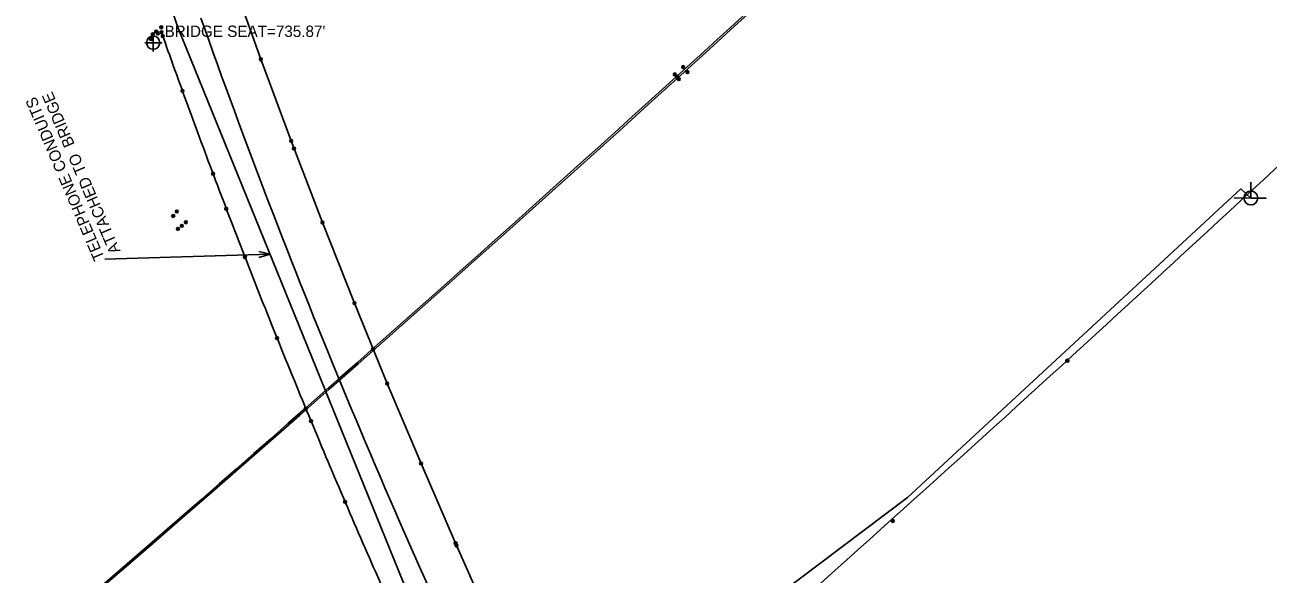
# Model space of a CAD drawing. Extents: x 1550153 to 1552579, y 809637 to 812160.
# Drawn here: x 1551716.6 to 1552155.6, y 810663.3 to 810857.2 of the extents above; entities that cross this region are included whole.
import ezdxf

# ---------------------------------------------------------------- set-up
doc = ezdxf.new("R2010")
doc.units = 0
for name, color, linetype in [('Default', 7, 'Continuous'), ('E_NCDOT_Horizontal_Alignment_Curve', 7, 'Continuous'), ('E_NCDOT_Horizontal_Alignment_Tick_Label', 7, 'Continuous'), ('Exist Right of Way Line', 7, 'Continuous'), ('Exist Roads EOP Other', 7, 'Continuous'), ('Exist Structure Major Bridge Seat Cogo Point CELL', 7, 'Continuous'), ('Exist Utilities Power Joint Use Telephone CELL', 7, 'Continuous'), ('Exist Utilities Telephone Text', 7, 'Continuous'), ('Exist Utilities Telephone UG Cable SUE LOS B', 7, 'Continuous'), ('Exist Utilities Telephone UG Cable SUE LOS C', 7, 'Continuous'), ('Exist Utilities Telephone UG FO SUE LOS B', 7, 'Continuous')]:
    doc.layers.add(name, color=color, linetype=linetype)

# ---------------------------------------------------------------- blocks, each defined once
blk = doc.blocks.new('SurveyPointCell')
at = {"layer": 'Default'}
for p, q in [((-0.5, 0), (0.5, 0)), ((0, -0.5), (0, 0.5))]:
    blk.add_line(p, q, dxfattribs=at)
blk.add_circle((0, 0), 0.5, dxfattribs=at)

msp = doc.modelspace()

# ---------------------------------------------------------------- linework, layer by layer
at = {"layer": 'Default'}
msp.add_line((1551761.92, 810850.87), (1551761.92, 810850.87), dxfattribs=at)
msp.add_arc((1544558.52, 818987.58), 11000, 308.905285, 313.48368, dxfattribs=at)
msp.add_arc((1544558.52, 818987.58), 11000, 308.905285, 313.48368, dxfattribs=at)
at = {"layer": 'E_NCDOT_Horizontal_Alignment_Curve'}
for centre, radius, start, end in [((1544245.73, 819324.67), 11459.16, 307.933611, 313.133611), ((1544245.73, 819324.67), 11459.16, 307.933611, 313.133611), ((1554277.17, 811742.97), 2650, 199.47344, 205.4841), ((1554277.17, 811742.97), 2650, 199.47344, 205.4841)]:
    msp.add_arc(centre, radius, start, end, dxfattribs=at)
at = {"layer": 'E_NCDOT_Horizontal_Alignment_Tick_Label'}
msp.add_arc((1544558.52, 818987.58), 11000, 308.905285, 313.48368, dxfattribs=at)
at = {"layer": 'Exist Right of Way Line'}
msp.add_arc((1544245.71, 819324.7), 11626.16, 311.427072, 313.124848, dxfattribs=at)
at = {"layer": 'Exist Roads EOP Other'}
for p, q in [((1551789.07, 810875.41), (1551799.93, 810844.99)), ((1551789.07, 810875.41), (1551799.93, 810844.99)), ((1551765.33, 810853.14), (1551764.85, 810854.54)), ((1551765.33, 810853.14), (1551764.85, 810854.54)), ((1551799.93, 810844.99), (1551810.62, 810816.24)), ((1551799.93, 810844.99), (1551810.62, 810816.24)), ((1551810.62, 810816.24), (1551821.7, 810787.42)), ((1551810.62, 810816.24), (1551821.7, 810787.42)), ((1551821.7, 810787.42), (1551832.98, 810758.95)), ((1551821.7, 810787.42), (1551832.98, 810758.95)), ((1551832.98, 810758.95), (1551844.52, 810730.57)), ((1551832.98, 810758.95), (1551844.52, 810730.57)), ((1551844.52, 810730.57), (1551856.47, 810702.36)), ((1551844.52, 810730.57), (1551856.47, 810702.36)), ((1551856.47, 810702.36), (1551868.68, 810674.18)), ((1551856.47, 810702.36), (1551868.68, 810674.18)), ((1551868.68, 810674.18), (1551881.33, 810645.63)), ((1551868.68, 810674.18), (1551881.33, 810645.63))]:
    msp.add_line(p, q, dxfattribs=at)
msp.add_open_spline([(1551864.83, 810610.13), (1551863.85, 810612.31), (1551860.28, 810619.56), (1551853.04, 810635.92), (1551842.19, 810659.92), (1551829.81, 810688.31), (1551817.52, 810717.53), (1551805.7, 810746.3), (1551794.16, 810775.4), (1551783.02, 810804.5), (1551773.45, 810830.52), (1551767.56, 810846.7), (1551765.33, 810853.14)], degree=3, dxfattribs=at)
msp.add_open_spline([(1551864.83, 810610.13), (1551863.85, 810612.31), (1551860.28, 810619.56), (1551853.04, 810635.92), (1551842.19, 810659.92), (1551829.81, 810688.31), (1551817.52, 810717.53), (1551805.7, 810746.3), (1551794.16, 810775.4), (1551783.02, 810804.5), (1551773.45, 810830.52), (1551767.56, 810846.7), (1551765.33, 810853.14)], degree=3, dxfattribs=at)
at = {"layer": 'Exist Structure Major Bridge Seat Cogo Point CELL'}
msp.add_lwpolyline([(1551761.92, 810853.87), (1551761.92, 810847.87), (1551761.92, 810850.87), (1551764.92, 810850.87), (1551758.92, 810850.87)], dxfattribs=at)
msp.add_circle((1551761.92, 810850.87), 2.34, dxfattribs=at)
at = {"layer": 'Exist Utilities Power Joint Use Telephone CELL'}
msp.add_line((1552149.46, 810796.05), (1552149.46, 810796.05), dxfattribs=at)
msp.add_lwpolyline([(1552143.52, 810796.05), (1552154.86, 810796.01), (1552149.46, 810796.03), (1552149.46, 810801.68)], dxfattribs=at)
msp.add_circle((1552149.46, 810796.06), 2.45, dxfattribs=at)
at = {"layer": 'Exist Utilities Telephone Text'}
for p, q in [((1551744.85, 810774.44), (1551803.2, 810776.19)), ((1551799.16, 810777.11), (1551803.2, 810776.19)), ((1551803.2, 810776.19), (1551799.2, 810775.1))]:
    msp.add_line(p, q, dxfattribs=at)
at = {"layer": 'Exist Utilities Telephone UG Cable SUE LOS B'}
msp.add_lwpolyline([(1551635.47, 811205.41), (1551654.84, 811204.95), (1551659.43, 811203.7), (1551662.57, 811201.11), (1551675.9, 811149.68), (1551694.16, 811082.62), (1551715.46, 811009.19), (1551741.91, 810920.73), (1551757.61, 810876.2), (1551761.94, 810865.34), (1551769.04, 810860.85), (1551770.5, 810856.61)], dxfattribs=at)
at = {"layer": 'Exist Utilities Telephone UG Cable SUE LOS C'}
msp.add_line((1551770.5, 810856.61), (1551869.65, 810612.8), dxfattribs=at)
at = {"layer": 'Exist Utilities Telephone UG FO SUE LOS B'}
msp.add_lwpolyline([(1552149.46, 810796.04), (1552145.97, 810799.24), (1552028.19, 810690.34), (1551912.49, 810603.16), (1551905.88, 810594.58), (1551906.11, 810591.78), (1551947.01, 810513.51), (1551988.11, 810434.51), (1552021.62, 810379.02), (1552029.45, 810370.42), (1552031.64, 810368.57), (1552034.29, 810368.77), (1552044.43, 810374.62)], dxfattribs=at)

# ---------------------------------------------------------------- block references
at = {"layer": 'Default'}
for p in [(1551761.8, 810853.85), (1551761.8, 810853.85), (1551762.99, 810854.8), (1551762.99, 810854.8), (1551763.52, 810854.16), (1551763.52, 810854.16), (1551764.78, 810856.29), (1551764.78, 810856.29), (1551764.85, 810854.54), (1551764.85, 810854.54), (1551761.14, 810852.14), (1551761.14, 810852.14), (1551761.37, 810852.33), (1551761.37, 810852.33), (1551765.33, 810853.14), (1551765.33, 810853.14), (1551799.93, 810844.99), (1551799.93, 810844.99), (1551949.05, 810842.27), (1551949.05, 810842.27), (1551950.54, 810840.51), (1551950.54, 810840.51), (1551946.07, 810839.67), (1551946.07, 810839.67), (1551946.87, 810838.87), (1551946.87, 810838.87), (1551947.52, 810837.99), (1551947.52, 810837.99), (1551772.23, 810833.89), (1551772.23, 810833.89), (1551810.62, 810816.24), (1551810.62, 810816.24), (1551811.6, 810813.51), (1551811.6, 810813.51), (1551783.05, 810804.62), (1551783.05, 810804.62), (1551787.73, 810792.26), (1551787.73, 810792.26), (1551769.01, 810789.72), (1551769.01, 810789.72), (1551770.24, 810791.27), (1551770.24, 810791.27), (1551770.65, 810785.16), (1551770.65, 810785.16), (1551772, 810786.25), (1551772, 810786.25), (1551773.46, 810787.48), (1551773.46, 810787.48), (1551821.7, 810787.42), (1551821.7, 810787.42), (1551794.32, 810775.18), (1551794.32, 810775.18), (1551832.98, 810758.95), (1551832.98, 810758.95), (1551805.64, 810746.61), (1551805.64, 810746.61), (1551839.54, 810742.74), (1551839.54, 810742.74), (1552084.68, 810738.63), (1552084.69, 810738.64), (1551844.52, 810730.57), (1551844.52, 810730.57), (1551815.81, 810721.71), (1551815.81, 810721.71), (1551817.65, 810717.31), (1551817.65, 810717.31), (1551856.47, 810702.36), (1551856.47, 810702.36), (1551829.66, 810688.83), (1551829.66, 810688.83), (1552023.01, 810682.06), (1552023.02, 810682.07), (1551868.68, 810674.18), (1551868.68, 810674.18), (1551869.01, 810673.34), (1551869.01, 810673.34)]:
    msp.add_blockref('SurveyPointCell', p, dxfattribs=at)

# ---------------------------------------------------------------- texts
msp.add_text("BRIDGE SEAT=735.87'", height=4.02, dxfattribs=at).set_placement((1551765.94, 810852.88))
at = {"layer": 'Exist Utilities Telephone Text'}
for s, p in [('ATTACHED TO  BRIDGE', (1551750.4, 810777.35)), ('TELEPHONE CONDUITS', (1551744.85, 810774.97))]:
    msp.add_text(s, height=4.02, rotation=113.1736, dxfattribs=at).set_placement(p)

doc.saveas('drawing.dxf')
